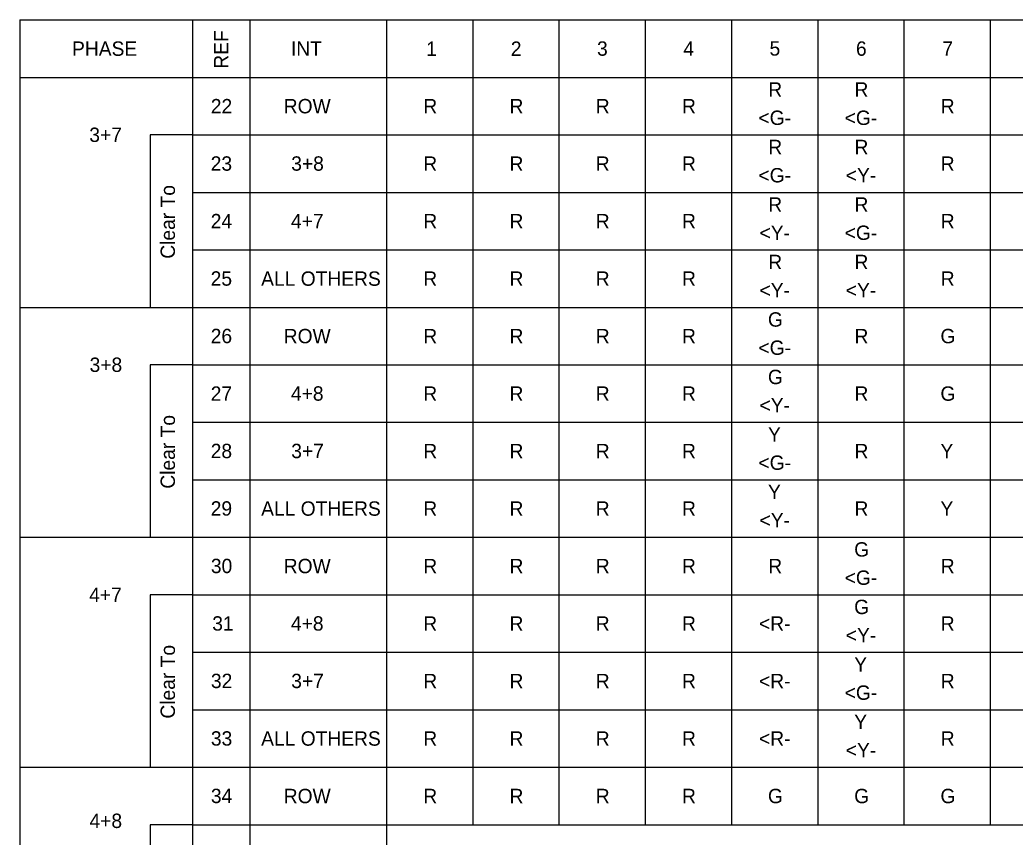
# Model space of a CAD drawing. Extents: x 515543 to 517243, y 660510 to 662861.
# Drawn here: x 516439.7 to 516908.5, y 660808.4 to 661193.4 of the extents above; entities that cross this region are included whole.
import ezdxf

# ---------------------------------------------------------------- set-up
doc = ezdxf.new("R2010")
doc.units = 0
doc.layers.add('Default', color=7, linetype='Continuous')

msp = doc.modelspace()

# ---------------------------------------------------------------- linework, layer by layer
at = {"layer": 'Default'}
for p, q in [((516439.72, 661193.38), (517130.34, 661193.38)), ((516439.72, 661193.38), (516439.72, 661057.96)), ((516520.97, 661193.38), (516520.97, 660597.54)), ((516548.05, 661193.38), (516548.05, 660597.54)), ((516612.41, 661193.38), (516612.41, 660597.54)), ((516653.03, 661193.38), (516653.03, 660814.21)), ((516693.66, 661193.38), (516693.66, 660814.21)), ((516734.28, 661193.38), (516734.28, 660814.21)), ((516774.91, 661193.38), (516774.91, 660814.21)), ((516815.53, 661193.38), (516815.53, 660814.21)), ((516856.16, 661193.38), (516856.16, 660814.21)), ((516896.78, 661193.38), (516896.78, 660814.21)), ((516439.72, 661166.29), (517130.34, 661166.29)), ((516520.97, 661139.21), (516501.15, 661139.21)), ((516501.15, 661139.21), (516501.15, 661057.96)), ((516520.97, 661139.21), (517018.66, 661139.21)), ((516520.97, 661112.13), (517018.66, 661112.13)), ((516693.66, 661112.13), (517018.66, 661112.13)), ((516520.97, 661085.04), (517018.66, 661085.04)), ((516439.72, 661057.96), (517130.34, 661057.96)), ((516439.72, 661057.96), (516439.72, 660949.63)), ((516520.97, 661057.96), (516683.47, 661057.96)), ((516520.97, 661030.88), (516501.15, 661030.88)), ((516501.15, 661030.88), (516501.15, 660949.63)), ((516520.97, 661030.88), (517018.66, 661030.88)), ((516520.97, 661003.79), (517018.66, 661003.79)), ((516693.66, 661003.79), (517018.66, 661003.79)), ((516520.97, 660976.71), (517018.66, 660976.71)), ((516439.72, 660949.63), (516439.72, 660841.29)), ((516439.72, 660949.63), (517130.34, 660949.63)), ((516520.97, 660922.54), (516501.15, 660922.54)), ((516520.97, 660922.54), (516501.15, 660922.54)), ((516501.15, 660922.54), (516501.15, 660841.29)), ((516520.97, 660922.54), (517008.47, 660922.54)), ((516520.97, 660922.54), (517018.66, 660922.54)), ((516520.97, 660895.46), (517018.66, 660895.46)), ((516520.97, 660895.46), (517018.66, 660895.46)), ((516693.66, 660895.46), (517018.66, 660895.46)), ((516693.66, 660895.46), (517018.66, 660895.46)), ((516520.97, 660868.38), (517008.47, 660868.38)), ((516520.97, 660868.38), (517018.66, 660868.38)), ((516439.72, 660841.29), (516439.72, 660732.96)), ((516439.72, 660841.29), (517130.34, 660841.29)), ((516520.97, 660814.21), (516501.15, 660814.21)), ((516520.97, 660814.21), (516501.15, 660814.21)), ((516501.15, 660814.21), (516501.15, 660732.96)), ((516520.97, 660814.21), (517008.47, 660814.21)), ((516520.97, 660814.21), (517018.66, 660814.21))]:
    msp.add_line(p, q, dxfattribs=at)

# ---------------------------------------------------------------- texts
for s, p in [('REF', (516537.9, 661170.37)), ('Clear To', (516512.76, 661080.86)), ('Clear To', (516512.76, 660972.53)), ('Clear To', (516512.76, 660864.2))]:
    msp.add_text(s, height=6.771, rotation=90, dxfattribs=at).set_placement(p)
for s, height, p in [('PHASE', 6.771, (516464.29, 661176.45)), ('INT', 6.771, (516567.4, 661176.45)), ('1', 6.77, (516631.15, 661176.44)), ('2', 6.77, (516670.96, 661176.44)), ('3', 6.77, (516711.59, 661176.49)), ('4', 6.77, (516752.23, 661176.45)), ('5', 6.77, (516792.84, 661176.55)), ('6', 6.77, (516833.55, 661176.49)), ('7', 6.77, (516874.23, 661176.5)), ('R', 6.77, (516792.24, 661157.2)), ('R', 6.77, (516832.86, 661157.2)), ('22', 6.771, (516529.64, 661149.35)), ('ROW', 6.771, (516564, 661149.36)), ('R', 6.77, (516629.74, 661149.37)), ('R', 6.77, (516670.36, 661149.37)), ('R', 6.77, (516710.99, 661149.37)), ('R', 6.77, (516751.61, 661149.37)), ('R', 6.77, (516873.49, 661149.37)), ('<G-', 6.771, (516787.61, 661143.89)), ('<G-', 6.771, (516828.23, 661143.89)), ('3+7', 6.771, (516472.4, 661135.87)), ('R', 6.77, (516792.24, 661130.12)), ('R', 6.77, (516832.86, 661130.12)), ('23', 6.771, (516529.6, 661122.33)), ('3+8', 6.771, (516567.52, 661122.33)), ('R', 6.77, (516629.74, 661122.28)), ('R', 6.77, (516670.36, 661122.28)), ('R', 6.77, (516710.99, 661122.28)), ('R', 6.77, (516751.61, 661122.28)), ('R', 6.77, (516873.49, 661122.28)), ('<G-', 6.771, (516787.61, 661116.81)), ('<Y-', 6.771, (516828.76, 661116.81)), ('R', 6.77, (516792.24, 661103.03)), ('R', 6.77, (516832.86, 661103.03)), ('24', 6.771, (516529.62, 661095.19)), ('4+7', 6.771, (516567.39, 661095.2)), ('R', 6.77, (516629.74, 661095.2)), ('R', 6.77, (516670.36, 661095.2)), ('R', 6.77, (516710.99, 661095.2)), ('R', 6.77, (516751.61, 661095.2)), ('R', 6.77, (516873.49, 661095.2)), ('<Y-', 6.771, (516788.13, 661089.72)), ('<G-', 6.771, (516828.23, 661089.72)), ('R', 6.77, (516792.24, 661075.95)), ('R', 6.77, (516832.86, 661075.95)), ('25', 6.771, (516529.58, 661068.16)), ('ALL OTHERS', 6.771, (516553.35, 661068.11)), ('R', 6.77, (516629.74, 661068.12)), ('R', 6.77, (516670.36, 661068.12)), ('R', 6.77, (516710.99, 661068.12)), ('R', 6.77, (516751.61, 661068.12)), ('R', 6.77, (516873.49, 661068.12)), ('<Y-', 6.771, (516788.13, 661062.64)), ('<Y-', 6.771, (516828.76, 661062.64)), ('G', 6.77, (516792.09, 661048.86)), ('26', 6.771, (516529.6, 661041.08)), ('ROW', 6.771, (516564, 661041.03)), ('R', 6.77, (516629.74, 661041.03)), ('R', 6.77, (516670.36, 661041.03)), ('R', 6.77, (516710.99, 661041.03)), ('R', 6.77, (516751.61, 661041.03)), ('R', 6.77, (516832.86, 661041.03)), ('G', 6.77, (516873.34, 661041.03)), ('<G-', 6.771, (516787.61, 661035.56)), ('3+8', 6.771, (516472.54, 661027.54)), ('G', 6.77, (516792.09, 661021.78)), ('27', 6.771, (516529.6, 661013.94)), ('4+8', 6.771, (516567.39, 661013.99)), ('R', 6.77, (516629.74, 661013.95)), ('R', 6.77, (516670.36, 661013.95)), ('R', 6.77, (516710.99, 661013.95)), ('R', 6.77, (516751.61, 661013.95)), ('R', 6.77, (516832.86, 661013.95)), ('G', 6.77, (516873.34, 661013.95)), ('<Y-', 6.771, (516788.13, 661008.47)), ('Y', 6.77, (516792.11, 660994.7)), ('28', 6.771, (516529.6, 660986.91)), ('3+7', 6.771, (516567.53, 660986.91)), ('R', 6.77, (516629.74, 660986.87)), ('R', 6.77, (516670.36, 660986.87)), ('R', 6.77, (516710.99, 660986.87)), ('R', 6.77, (516751.61, 660986.87)), ('R', 6.77, (516832.86, 660986.87)), ('Y', 6.77, (516873.36, 660986.87)), ('<G-', 6.771, (516787.61, 660981.39)), ('Y', 6.77, (516792.11, 660967.62)), ('29', 6.771, (516529.6, 660959.83)), ('ALL OTHERS', 6.771, (516553.35, 660959.78)), ('R', 6.77, (516629.74, 660959.78)), ('R', 6.77, (516670.36, 660959.78)), ('R', 6.77, (516710.99, 660959.78)), ('R', 6.77, (516751.61, 660959.78)), ('R', 6.77, (516832.86, 660959.78)), ('Y', 6.77, (516873.36, 660959.78)), ('<Y-', 6.771, (516788.13, 660954.31)), ('G', 6.77, (516832.71, 660940.53)), ('30', 6.771, (516529.68, 660932.74)), ('ROW', 6.771, (516564, 660932.7)), ('ROW', 6.771, (516564, 660932.7)), ('R', 6.77, (516629.74, 660932.7)), ('R', 6.77, (516670.36, 660932.7)), ('R', 6.77, (516710.99, 660932.7)), ('R', 6.77, (516751.61, 660932.7)), ('R', 6.77, (516792.24, 660932.7)), ('R', 6.77, (516873.49, 660932.7)), ('<G-', 6.771, (516828.23, 660927.22)), ('4+7', 6.771, (516472.35, 660919.16)), ('G', 6.77, (516832.71, 660913.45)), ('31', 6.771, (516530.32, 660905.66)), ('4+8', 6.771, (516567.39, 660905.66)), ('R', 6.77, (516629.74, 660905.62)), ('R', 6.77, (516670.36, 660905.62)), ('R', 6.77, (516710.99, 660905.62)), ('R', 6.77, (516751.61, 660905.62)), ('<R-', 6.771, (516787.87, 660905.62)), ('<R-', 6.771, (516787.87, 660905.62)), ('R', 6.77, (516873.49, 660905.62)), ('R', 6.77, (516873.49, 660905.62)), ('<Y-', 6.771, (516828.76, 660900.14)), ('Y', 6.77, (516832.74, 660886.37)), ('32', 6.771, (516529.7, 660878.58)), ('3+7', 6.771, (516567.53, 660878.58)), ('R', 6.77, (516629.74, 660878.53)), ('R', 6.77, (516670.36, 660878.53)), ('R', 6.77, (516710.99, 660878.53)), ('R', 6.77, (516751.61, 660878.53)), ('<R-', 6.771, (516787.87, 660878.53)), ('<R-', 6.771, (516787.87, 660878.53)), ('R', 6.77, (516873.49, 660878.53)), ('R', 6.77, (516873.49, 660878.53)), ('<G-', 6.771, (516828.23, 660873.06)), ('Y', 6.77, (516832.74, 660859.28)), ('33', 6.771, (516529.67, 660851.49)), ('ALL OTHERS', 6.771, (516553.35, 660851.45)), ('ALL OTHERS', 6.771, (516553.35, 660851.45)), ('R', 6.77, (516629.74, 660851.45)), ('R', 6.77, (516670.36, 660851.45)), ('R', 6.77, (516710.99, 660851.45)), ('R', 6.77, (516751.61, 660851.45)), ('<R-', 6.771, (516787.87, 660851.45)), ('<R-', 6.771, (516787.87, 660851.45)), ('R', 6.77, (516873.49, 660851.45)), ('R', 6.77, (516873.49, 660851.45)), ('<Y-', 6.771, (516828.76, 660845.97)), ('34', 6.771, (516529.68, 660824.41)), ('ROW', 6.771, (516564, 660824.36)), ('ROW', 6.771, (516564, 660824.36)), ('R', 6.77, (516629.74, 660824.37)), ('R', 6.77, (516670.36, 660824.37)), ('R', 6.77, (516710.99, 660824.37)), ('R', 6.77, (516751.61, 660824.37)), ('G', 6.77, (516792.09, 660824.36)), ('G', 6.77, (516832.71, 660824.36)), ('G', 6.77, (516873.34, 660824.36)), ('4+8', 6.771, (516472.5, 660812.67))]:
    msp.add_text(s, height=height, dxfattribs=at).set_placement(p)

doc.saveas('drawing.dxf')
